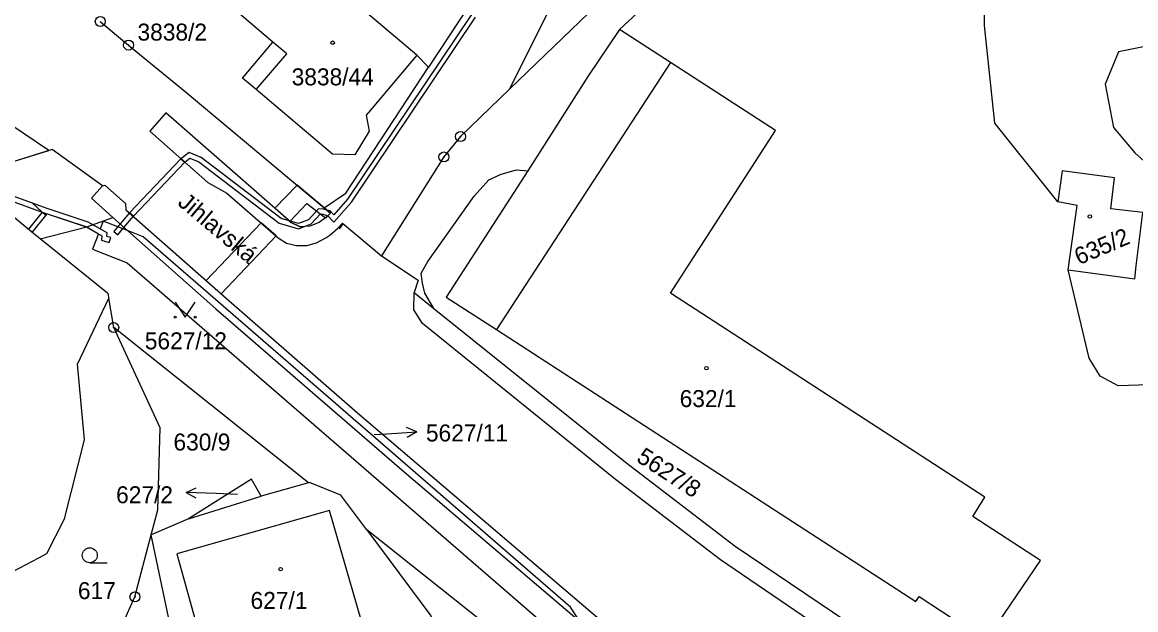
# Model space of a CAD drawing. Extents: x -644096 to -634268, y -1141430 to -1133463.
# Drawn here: x -640055.5 to -639944.1, y -1138008 to -1137949.2 of the extents above; entities that cross this region are included whole.
import ezdxf

# ---------------------------------------------------------------- set-up
doc = ezdxf.new("R2010")
doc.units = 0
for name, color, linetype in [('_CIVIL_CONSTRUCTION', 7, 'Continuous'), ('B_Hranice _3D', 7, 'Continuous'), ('M_Svah_Nasyp', 7, 'Continuous'), ('M_Svah_Zarez', 7, 'Continuous'), ('spodek_zarez', 7, 'Continuous'), ('svrsek_osa_sjezdy', 7, 'Continuous'), ('svrsek_osa_VRT', 7, 'Continuous'), ('svrsek_popisy_VRT', 7, 'Continuous'), ('terminal_VRT', 7, 'Continuous')]:
    doc.layers.add(name, color=color, linetype=linetype)

msp = doc.modelspace()

# ---------------------------------------------------------------- linework, layer by layer
at = {"layer": '_CIVIL_CONSTRUCTION'}
for centre, radius in [((-640047.7, -1137949.1), 0.5), ((-640044.87, -1137951.46), 0.5), ((-640044.87, -1137951.46), 0.0303), ((-640011.67, -1137960.62), 0.5), ((-640011.67, -1137960.62), 0.0303), ((-640013.33, -1137962.66), 0.5), ((-640013.33, -1137962.66), 0.0303), ((-640046.36, -1137979.74), 0.5), ((-640046.36, -1137979.74), 0.0303), ((-640044.23, -1138006.7), 0.5), ((-640044.23, -1138006.7), 0.0303)]:
    msp.add_circle(centre, radius, dxfattribs=at)
at = {"layer": 'B_Hranice _3D'}
for points in [[(-640128.81, -1137899.7), (-640066.47, -1137956.39), (-640061.76, -1137960.68), (-640059.53, -1137962.7), (-640060.92, -1137960.21), (-640056.52, -1137963.16), (-640052.85, -1137962.01), (-640059.25, -1137957.72), (-640061.7, -1137956.08), (-640065.1, -1137952.83), (-640087.02, -1137934.09), (-640123.64, -1137904)], [(-640044.39, -1137968.59), (-640039.26, -1137963.18), (-640039.64, -1137962.84), (-640044.77, -1137968.26)], [(-640027.26, -1137969.62), (-640027.7, -1137969.65), (-640028.6, -1137969.23), (-640028.8, -1137969.06), (-640029.6, -1137968.82), (-640037.6, -1137962.71), (-640038.81, -1137962.2), (-640039.64, -1137962.84), (-640039.26, -1137963.18), (-640038.73, -1137962.78), (-640037.86, -1137963.15), (-640029.82, -1137969.28), (-640027.86, -1137969.85)], [(-640030.23, -1137967.8), (-640028.73, -1137969.12), (-640027.03, -1137967.33), (-640025.16, -1137968.75), (-640025.04, -1137968.66), (-640024.93, -1137968.55), (-640024.66, -1137968.29), (-640025.3, -1137967.76), (-640028.02, -1137965.48)], [(-640054.48, -1137967.29), (-640053.14, -1137968.51), (-640053.01, -1137968.35), (-640049.13, -1137969.64), (-640047.53, -1137970.54), (-640047.58, -1137971), (-640046.8, -1137971.21), (-640046.66, -1137970.73), (-640047.04, -1137970.62), (-640047.01, -1137970.26), (-640048.93, -1137969.18), (-640053.02, -1137967.82)], [(-640053.51, -1137968.18), (-640054.89, -1137969.89), (-640054.5, -1137970.21), (-640053.14, -1137968.51)], [(-640044.39, -1137968.59), (-640044.77, -1137968.26), (-640045.7, -1137969.37), (-640046.34, -1137970.13), (-640045.96, -1137970.45), (-640045.33, -1137969.71)], [(-640027.26, -1137969.62), (-640026.61, -1137969.37), (-640025.67, -1137968.36), (-640025.44, -1137968.38), (-640024.93, -1137968.55), (-640024.66, -1137968.29), (-640025.05, -1137967.97), (-640025.36, -1137967.88), (-640025.87, -1137967.84), (-640026.89, -1137968.95), (-640027.88, -1137969.33), (-640028.8, -1137969.06), (-640028.6, -1137969.23), (-640027.7, -1137969.65)], [(-640037.11, -1137975.04), (-640035.62, -1137976.36), (-640030.11, -1137970.57), (-640031.62, -1137969.26)], [(-640023.88, -1137969.72), (-640023.75, -1137969.82), (-640023.42, -1137969.34), (-640023.49, -1137969.28)]]:
    msp.add_lwpolyline(points, close=True, dxfattribs=at)
for points in [[(-640010.58, -1137948.4), (-640022.99, -1137966.89), (-640024.35, -1137968.45), (-640024.72, -1137968.06), (-640025.05, -1137967.97), (-640024.66, -1137968.29), (-640024.93, -1137968.55), (-640024.33, -1137969.19), (-640022.59, -1137967.19), (-640010.16, -1137948.66)], [(-640059.38, -1137966.05), (-640053.51, -1137968.18), (-640054.48, -1137967.29), (-640059.12, -1137965.61)], [(-640059.38, -1137966.05), (-640053.51, -1137968.18), (-640049.06, -1137969.66), (-640047.89, -1137970.34), (-640048.49, -1137971.88), (-640045, -1137973.26), (-640002.95, -1138009.73)], [(-639999.73, -1138009.16), (-640000.67, -1138007.73), (-640043.42, -1137970.66), (-640044.92, -1137970.07), (-640047.4, -1137969.09), (-640047.7, -1137969.87), (-640048.93, -1137969.18), (-640053.02, -1137967.82), (-640054.48, -1137967.29), (-640059.12, -1137965.61)]]:
    msp.add_lwpolyline(points, dxfattribs=at)
at = {"layer": 'M_Svah_Nasyp'}
for p, q in [((-640029.05, -1137952.32), (-640030.44, -1137951.16)), ((-640032.1, -1137955.9), (-640029.05, -1137952.32)), ((-639990.67, -1137953.19), (-640008.06, -1137979.94))]:
    msp.add_line(p, q, dxfattribs=at)
at = {"layer": 'M_Svah_Zarez'}
for centre in [(-640024.45, -1137951.22), (-639948.72, -1137968.62), (-639987.07, -1137983.8), (-640029.66, -1138003.93)]:
    msp.add_circle(centre, 0.175, dxfattribs=at)
at = {"layer": 'spodek_zarez'}
msp.add_circle((-638683.07, -1137056.85), 1378.08, dxfattribs=at)
at = {"layer": 'svrsek_osa_sjezdy'}
msp.add_line((-640048.75, -1138003.29), (-640047, -1138003.29), dxfattribs=at)
msp.add_lwpolyline([(-640040.2, -1137977.2), (-640039.2, -1137978.7), (-640038.2, -1137977.2)], dxfattribs=at)
for centre, radius in [((-640040.2, -1137978.7), 0.1), ((-640038.2, -1137978.7), 0.1), ((-640048.75, -1138002.54), 0.75)]:
    msp.add_circle(centre, radius, dxfattribs=at)
at = {"layer": 'svrsek_popisy_VRT'}
for p, q in [((-640016.05, -1137990.17), (-640017.08, -1137989.74)), ((-640020.29, -1137990.46), (-640019.04, -1137990.38)), ((-640019.04, -1137990.38), (-640016.05, -1137990.17)), ((-640016.05, -1137990.17), (-640017.01, -1137990.74)), ((-640039.12, -1137996.26), (-640038.1, -1137995.79)), ((-640036.12, -1137996.36), (-640039.12, -1137996.26)), ((-640039.12, -1137996.26), (-640038.14, -1137996.79)), ((-640033.99, -1137996.46), (-640036.12, -1137996.36))]:
    msp.add_line(p, q, dxfattribs=at)
at = {"layer": 'terminal_VRT'}
for p, q in [((-640016.04, -1137952.48), (-640023.7, -1137945.97)), ((-640014.87, -1137953.68), (-640016.04, -1137952.48)), ((-640039.2, -1137956.12), (-640025.3, -1137967.76)), ((-640016.31, -1137976.24), (-640014.33, -1137977.83)), ((-640046.36, -1137979.74), (-640046.83, -1137976.81)), ((-640026.88, -1137995.28), (-640046.36, -1137979.74)), ((-640026.88, -1137995.28), (-640031.6, -1137996.62)), ((-640038.88, -1137998.9), (-640031.6, -1137996.62)), ((-640038.88, -1137998.9), (-640042.61, -1138000.48)), ((-639998.55, -1138017.87), (-640021.05, -1138000))]:
    msp.add_line(p, q, dxfattribs=at)
for points in [[(-640047.49, -1137965.54), (-640052.53, -1137961.91), (-640058.39, -1137963.74), (-640142.98, -1137886.82), (-640150.7, -1137879.95), (-640201.85, -1137835.66), (-640224.08, -1137816.08), (-640264.87, -1137782.17), (-640269.07, -1137778.31), (-640271.13, -1137776.42)], [(-640009.62, -1137902.46), (-640007.34, -1137905.39), (-640002.03, -1137916.46), (-640000.83, -1137923.06), (-640001.45, -1137929.66), (-640004.72, -1137937.47), (-640007.71, -1137942.75), (-640014.87, -1137953.68)], [(-639980.72, -1137930.7), (-639981.87, -1137931.81), (-639988.83, -1137938.55), (-639994.45, -1137944), (-640006.73, -1137955.85)], [(-640006.73, -1137955.85), (-640001.88, -1137946.03), (-639999.03, -1137940.91), (-639998.09, -1137939.06), (-639996.45, -1137935.65)], [(-640016.04, -1137952.48), (-640020.88, -1137958.21), (-640021.1, -1137958.47), (-640020.81, -1137960.07), (-640022.23, -1137962.46), (-640024.47, -1137962.38), (-640032.1, -1137955.9), (-640033.47, -1137954.76), (-640030.44, -1137951.16), (-640038.94, -1137943.88), (-640033.74, -1137937.74), (-640023.89, -1137946.19), (-640023.7, -1137945.97)], [(-639951.93, -1137967.16), (-639958.24, -1137959.29), (-639959.25, -1137949.49), (-639959.34, -1137940.4)], [(-639985.68, -1137941.07), (-639986.44, -1137941.22), (-639995.75, -1137949.89)], [(-640047.7, -1137949.1), (-640044.87, -1137951.46), (-640039.2, -1137956.12)], [(-639995.75, -1137949.89), (-639998.93, -1137954.6), (-640004.93, -1137964.06)], [(-639959.08, -1138011.07), (-639953.65, -1138003.05), (-639960.44, -1137998.65), (-639959.21, -1137996.72), (-639990.67, -1137976.29), (-639980.17, -1137960.02), (-639990.67, -1137953.19), (-639995.75, -1137949.89)], [(-639903.12, -1137966.31), (-639919.24, -1137964.15), (-639917.88, -1137955.62), (-639940.32, -1137951.59), (-639943.2, -1137951.6), (-639945.84, -1137952.15), (-639947.18, -1137955.36), (-639946.34, -1137959.7), (-639944.22, -1137962.25), (-639940.48, -1137965.57), (-639940.63, -1137966.76)], [(-640025.3, -1137967.76), (-640023.13, -1137966.3), (-640014.87, -1137953.68)], [(-640006.73, -1137955.85), (-640011.67, -1137960.62), (-640013.33, -1137962.66), (-640019.56, -1137972.57)], [(-640025.3, -1137967.76), (-640024.66, -1137968.29), (-640025.04, -1137968.66), (-640025.81, -1137969.21), (-640026.73, -1137969.58), (-640027.7, -1137969.65), (-640028.6, -1137969.23), (-640041.16, -1137958.23), (-640042.74, -1137960.09), (-640036.95, -1137965.23), (-640035.03, -1137966.28), (-640029.91, -1137970.75), (-640029.06, -1137971.28), (-640028.07, -1137971.54), (-640027.04, -1137971.52), (-640026.06, -1137971.25), (-640025.15, -1137970.77), (-640024.73, -1137970.48), (-640023.96, -1137969.81), (-640023.49, -1137969.28), (-640019.56, -1137972.57)], [(-640053.73, -1137970.84), (-640054.38, -1137970.31), (-640065.24, -1137961.35)], [(-640014.33, -1137977.83), (-640015.23, -1137976.29), (-640015.46, -1137975.31), (-640015.59, -1137974.28), (-640014.94, -1137973.13), (-640010.3, -1137966.57), (-640008.82, -1137964.96), (-640007.59, -1137964.38), (-640006.08, -1137963.95), (-640004.93, -1137964.06)], [(-640004.93, -1137964.06), (-640013.12, -1137976.68), (-640008.06, -1137979.94), (-639966.11, -1138007.17), (-639965.79, -1138006.67), (-639959.08, -1138011.07)], [(-639950.9, -1137973.97), (-639944.22, -1137974.85), (-639944.1, -1137973.55), (-639943.42, -1137968.23), (-639946.62, -1137967.84), (-639946.24, -1137964.75), (-639951.5, -1137964.06), (-639951.93, -1137967.16)], [(-640046.43, -1137968.73), (-640048.59, -1137966.8), (-640047.49, -1137965.54)], [(-640047.49, -1137965.54), (-640047.26, -1137965.5), (-640045.19, -1137967.31), (-640045.13, -1137967.94), (-640035.12, -1137976.8), (-640021.96, -1137988.27), (-639996.18, -1138010.31), (-639994.93, -1138011.88), (-639993.98, -1138013.66), (-639993.64, -1138014.58), (-639993.47, -1138015.59), (-639993.55, -1138016.59), (-639993.88, -1138017.54), (-639994.48, -1138018.37), (-639995.34, -1138018.88), (-639996.82, -1138019.46)], [(-639950.9, -1137973.97), (-639950, -1137967.52), (-639951.93, -1137967.16)], [(-640053.73, -1137970.84), (-640049.06, -1137969.66), (-640046.43, -1137968.73)], [(-640046.43, -1137968.73), (-640036.13, -1137977.87), (-640017.31, -1137994.18), (-639997.58, -1138011), (-639996.25, -1138012.46), (-639995.31, -1138014.19), (-639994.88, -1138015.75), (-639994.94, -1138016.38), (-639995.17, -1138016.95), (-639995.92, -1138017.6), (-639998.02, -1138018.36)], [(-640046.83, -1137976.81), (-640046.89, -1137976.39), (-640046.99, -1137976.31), (-640053.73, -1137970.84)], [(-640019.56, -1137972.57), (-640016.12, -1137974.87), (-640015.9, -1137975.01), (-640016.31, -1137976.24)], [(-639941.66, -1137983.06), (-639942.8, -1137985.49), (-639945.88, -1137985.58), (-639947.69, -1137984.6), (-639948.78, -1137982.81), (-639950.9, -1137973.97)], [(-639944.93, -1138029.49), (-639953.93, -1138024.04), (-639961.88, -1138019.22), (-639985.67, -1138002.99), (-639996.15, -1137994.95), (-640015.48, -1137979.34), (-640016.34, -1137977.98), (-640016.31, -1137976.24)], [(-640075.31, -1138014.74), (-640056.37, -1138004.13), (-640053.85, -1138002.78), (-640053.04, -1138002.35), (-640051.28, -1137998.88), (-640049.28, -1137990.98), (-640049.97, -1137983.41), (-640046.83, -1137976.81)], [(-640014.33, -1137977.83), (-639995.17, -1137993.2), (-639984.21, -1138001.63), (-639959.2, -1138018.5)], [(-640042.61, -1138000.48), (-640041.93, -1137997.98), (-640041.71, -1137989.77), (-640046.36, -1137979.74)], [(-640031.6, -1137996.62), (-640032.59, -1137994.93), (-640038.88, -1137998.9)], [(-640021.05, -1138000), (-640023.64, -1137996.51), (-640026.79, -1137995.25), (-640026.88, -1137995.28)], [(-640037.66, -1138015.07), (-640037.27, -1138016.49), (-640016.02, -1138010.58), (-640016.41, -1138009.16), (-640021.22, -1138010.41), (-640024.76, -1137998.06), (-640040.04, -1138002.41), (-640036.6, -1138014.78), (-640037.66, -1138015.07)], [(-640046.45, -1138011.61), (-640044.23, -1138006.7), (-640042.61, -1138000.48)], [(-640021.05, -1138000), (-640014.65, -1138008.61), (-640013.58, -1138011.28), (-640016.28, -1138015.79), (-640037.71, -1138021.32), (-640039.13, -1138016.98), (-640042.61, -1138000.48)]]:
    msp.add_lwpolyline(points, dxfattribs=at)

# ---------------------------------------------------------------- texts
at = {"layer": 'svrsek_osa_VRT'}
for s, p in [('3838/2', (-640043.98, -1137951.01)), ('3838/44', (-640028.56, -1137955.49)), ('5627/12', (-640043.25, -1137981.92)), ('632/1', (-639989.75, -1137987.7)), ('5627/11', (-640015.13, -1137991.14)), ('630/9', (-640040.38, -1137992.05)), ('627/2', (-640046.12, -1137997.33)), ('617', (-640049.94, -1138006.93)), ('627/1', (-640032.67, -1138007.91))]:
    msp.add_text(s, height=1.7, dxfattribs=at).set_placement(p)
for s, rotation, p in [('635/2', 23, (-639949.81, -1137973.5)), ('5627/8', 327, (-639994.18, -1137993.07))]:
    msp.add_text(s, height=1.7, rotation=rotation, dxfattribs=at).set_placement(p)
at = {"layer": 'svrsek_popisy_VRT'}
msp.add_text('Jihlavská', height=1.7, rotation=320, dxfattribs=at).set_placement((-640040.06, -1137967.4))

doc.saveas('drawing.dxf')
